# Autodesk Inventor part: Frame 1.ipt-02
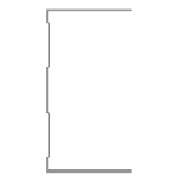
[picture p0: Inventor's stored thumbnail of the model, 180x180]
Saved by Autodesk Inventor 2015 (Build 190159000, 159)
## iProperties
IsCustomPart: 1
Created: 2015-04
Part Number: Frame 1.ipt-02
Material: Aluminum 6061
Description: Kévin Novo
Document SubType Name: Modeling
Standard: Kevin
Designer: suporte
Standards Organization: Kevin
Language: en-US
Size Designation: (Unnamed 2)
Categories: <MemberInstance><Categories><Category DisplayName="Structural Shapes" InternalName="089c4875-fa83-4c05-b084-43b9cc11f5ed" Mnemonic="GRDR"><CategoryParameter Dis
Density: 2.7 g/cm^3
Appearance: Aluminum - Flat
_CCFamilyMember: 2
_CCFamilyDisplayName: Kévin - Kévin Novo
_FrameMemberDoc: Frame Member File
_Version: 15.0.0
_GetPNFromCC: 1
G_W: 50,000 mm
G_H: 75,000 mm
G_L: 742,325 mm
+1278F890-8875-45A9-BBA4-B9D5376CE797+CUTDETAIL1: Cut
+5C76CBEB-8B41-4733-85A3-2AE3D2FC03BA+CUTDETAIL2: Miter 67,51 deg
Author: suporte
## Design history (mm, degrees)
node "Start Plane"
node "End Plane"
sketch "Sketch"
  geometry: L1 (24.7, 37.5)-(24.7, 36.9); L2 (24.7, 36.9)-(-24.7, 36.9); L3 (-24.7, -36.9)-(24.7, -36.9); L4 (24.7, -36.9)-(24.7, -37.5); L5 (24.7, -37.5)-(-25.3, -37.5); L6 (-25.3, 37.5)-(24.7, 37.5); L7 (-24.7, 36.9)-(-24.7, 31.9); L8 (-24.7, 31.9)-(-23.3, 30.5); L9 (-23.3, 30.5)-(-23.3, 10.934); L10 (-23.3, 10.934)-(-24.7, 9.534); L11 (-24.7, 9.534)-(-24.7, -9.534); L12 (-24.7, -9.534)-(-23.3, -10.934); L13 (-23.3, -10.934)-(-23.3, -30.5); L14 (-23.3, -30.5)-(-24.7, -31.9); L15 (-24.7, -31.9)-(-24.7, -36.9); L16 (-25.3, -37.5)-(-25.3, -31.651); L17 (-25.3, -31.651)-(-23.9, -30.251); L18 (-23.9, -30.251)-(-23.9, -11.183); L19 (-23.9, -11.183)-(-25.3, -9.783); L20 (-25.3, -9.783)-(-25.3, 9.783); L21 (-25.3, 9.783)-(-23.9, 11.183); L22 (-23.9, 11.183)-(-23.9, 30.251); L23 (-23.9, 30.251)-(-25.3, 31.651); L24 (-25.3, 31.651)-(-25.3, 37.5); L25 (-25.3, 0)-(30.37, 0); 3 further points
  constraints: 50 end point, 10 point on line, 9 parallel, 5 perpendicular, 4 equal length, 3 midpoint, 3 vertical, 2 vertical alignment, 1 collinear, 1 horizontal, 1 horizontal alignment
  dimensions: "d3" = 0.6 distance of L1.start L1.end (= d6); "d5" = 75 distance between parallel lines of L5 L6; "d6" = 0.6 distance between parallel lines of L24 L7 (= d8); "d7" = 0.6 distance between parallel lines of L8 L23 (= d8); "d8" = 0.6 distance between parallel lines of L22 L9 (= d12); "Espessura" = 0.6 distance between parallel lines of L17 L14; "d10" = 0.6 distance between parallel lines of L13 L18 (= Espessura); "d11" = 0.6 distance between parallel lines of L12 L19 (= Espessura); "d12" = 0.6 distance between parallel lines of L21 L10 (= d11); "d13" = 5 distance of L2.end L7.end; "d15" = 135 deg angle of L9 L8; "d16" = 2 distance between parallel lines of L24 L9; "d17" = 50 distance of L6.start L1.start
extrude "Body" join sketch "Sketch" stored distance "d24" = 0.13; taper "d25" = 0 deg
node "Driven Length"
  sketch "Sketch10"
    geometry: L1 (0, 0)-(10, 0) reference
    constraints: 2 end point, 1 horizontal
  workplane "Work Plane7"
  sketch "Sketch11"
    geometry: L1 (-2, -36.226)-(12, -36.226) reference; L2 (-2, 706.099)-(12, 706.099) reference
    dimensions: "d27" = 742.32488 distance between parallel lines of L1 L2 (derived)
workplane "Work Plane8"
split "Split1"
workplane "Work Plane9"
split "Split2"
body "Solid1"
other parameters: "tamanho" = 718.59902, "G_OFFSET_START" = 36.22585 [user parameter; used in 1 equation term], "G_OFFSET_END" = -12.5 [user parameter; used in 1 equation term], "d22" = -36.22585 (= -G_OFFSET_START), "d23" = 706.09902 (= tamanho + G_OFFSET_END), "G_L" = 742.32488 (= d27) [user parameter], "d34" = 90 deg
